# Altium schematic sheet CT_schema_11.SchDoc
size 274 x 160 mm
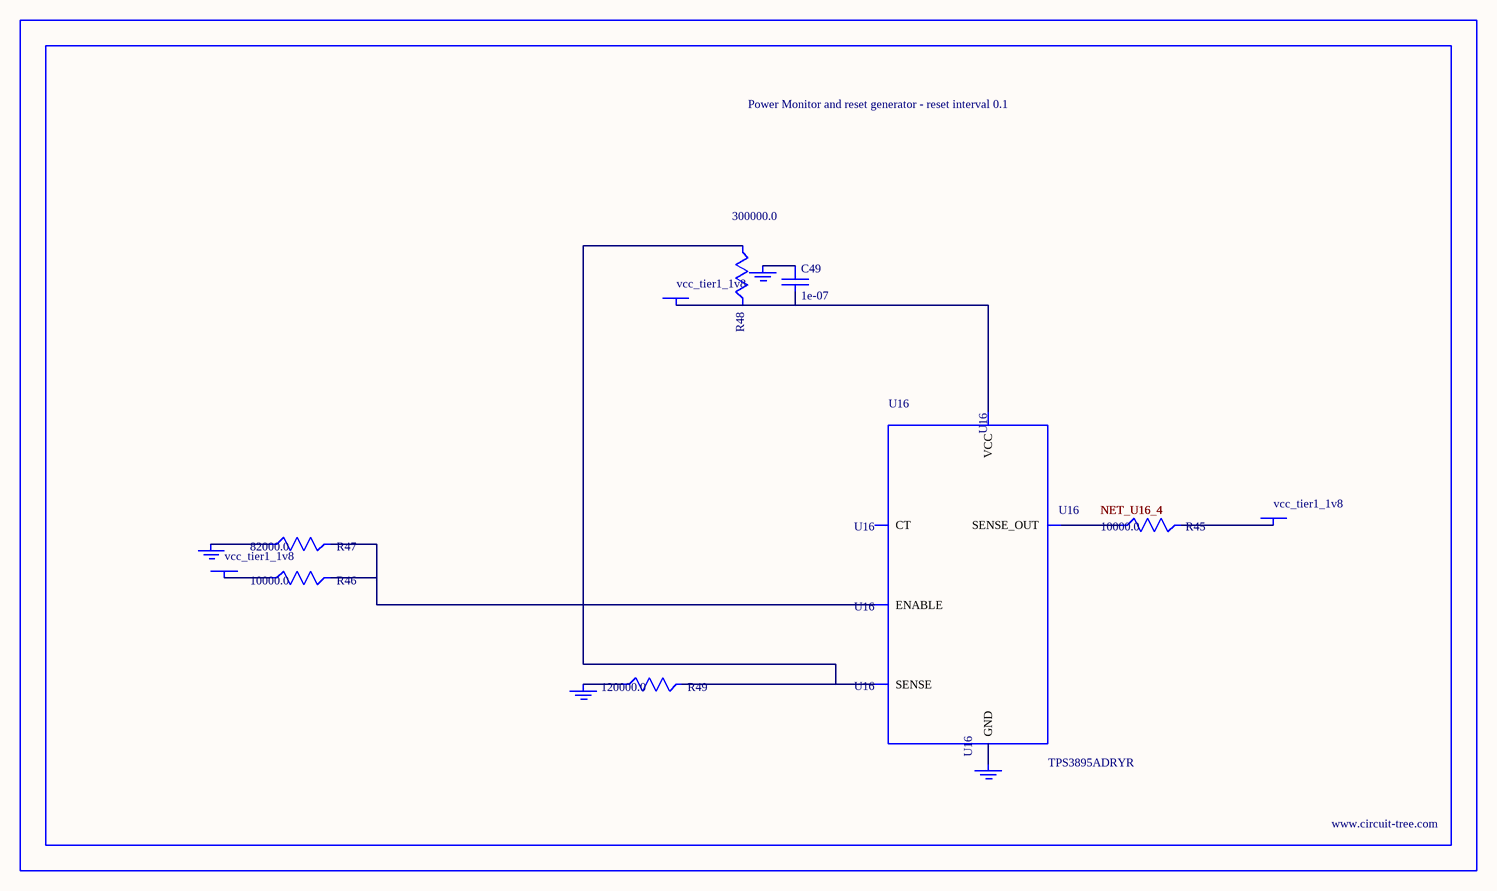
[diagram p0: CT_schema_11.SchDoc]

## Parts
BORDER10  (no value)
C49  1e-07  [C0402]
GND_INSTANCE_10_0  (no value)
GND_INSTANCE_10_1  (no value)
GND_INSTANCE_10_2  (no value)
GND_INSTANCE_10_3  (no value)
POWER_INSTANCE_10_0  vcc_tier1_1v8
POWER_INSTANCE_10_1  vcc_tier1_1v8
POWER_INSTANCE_10_2  vcc_tier1_1v8
R45  10000.0  [R0603]
R46  10000.0  [R0603]
R47  82000.0  [R0603]
R48  300000.0  [R0603]
R49  120000.0  [R0603]
U16  TPS3895ADRYR  [SON-6]

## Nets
NetC49_1: C49.1 GND_INSTANCE_10_2.0(GND)
NetC49_2: C49.2 POWER_INSTANCE_10_2.0(PWR) R48.2 U16.6(VCC)
NetGND_INSTANCE_10_0_0: GND_INSTANCE_10_0.0(GND) R47.1
NetGND_INSTANCE_10_1_0: GND_INSTANCE_10_1.0(GND) R49.1
NetGND_INSTANCE_10_3_0: GND_INSTANCE_10_3.0(GND) U16.2(GND)
NetPOWER_INSTANCE_10_0_0: POWER_INSTANCE_10_0.0(PWR) R46.1
NetPOWER_INSTANCE_10_1_0: POWER_INSTANCE_10_1.0(PWR) R45.2
NetR45_1: R45.1 U16.4(SENSE_OUT)
NetR46_2: R46.2 R47.2 U16.1(ENABLE)
NetR48_1: R48.1 R49.2 U16.3(SENSE)

Not connected (* = marked no-connect by the designer): U16 5(CT)

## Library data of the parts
BORDER10 = BORDER_PAGE10
C49 = C0402C104K3RACTU
GND_INSTANCE_10_0-GND_INSTANCE_10_3 = GND
POWER_INSTANCE_10_0-POWER_INSTANCE_10_2 = PWR
R45 R46 = RC0603JR-0710KL
R47 = RC0603JR-0782KL
R48 = RC0603JR-07300KL
R49 = RC0603JR-07120KL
